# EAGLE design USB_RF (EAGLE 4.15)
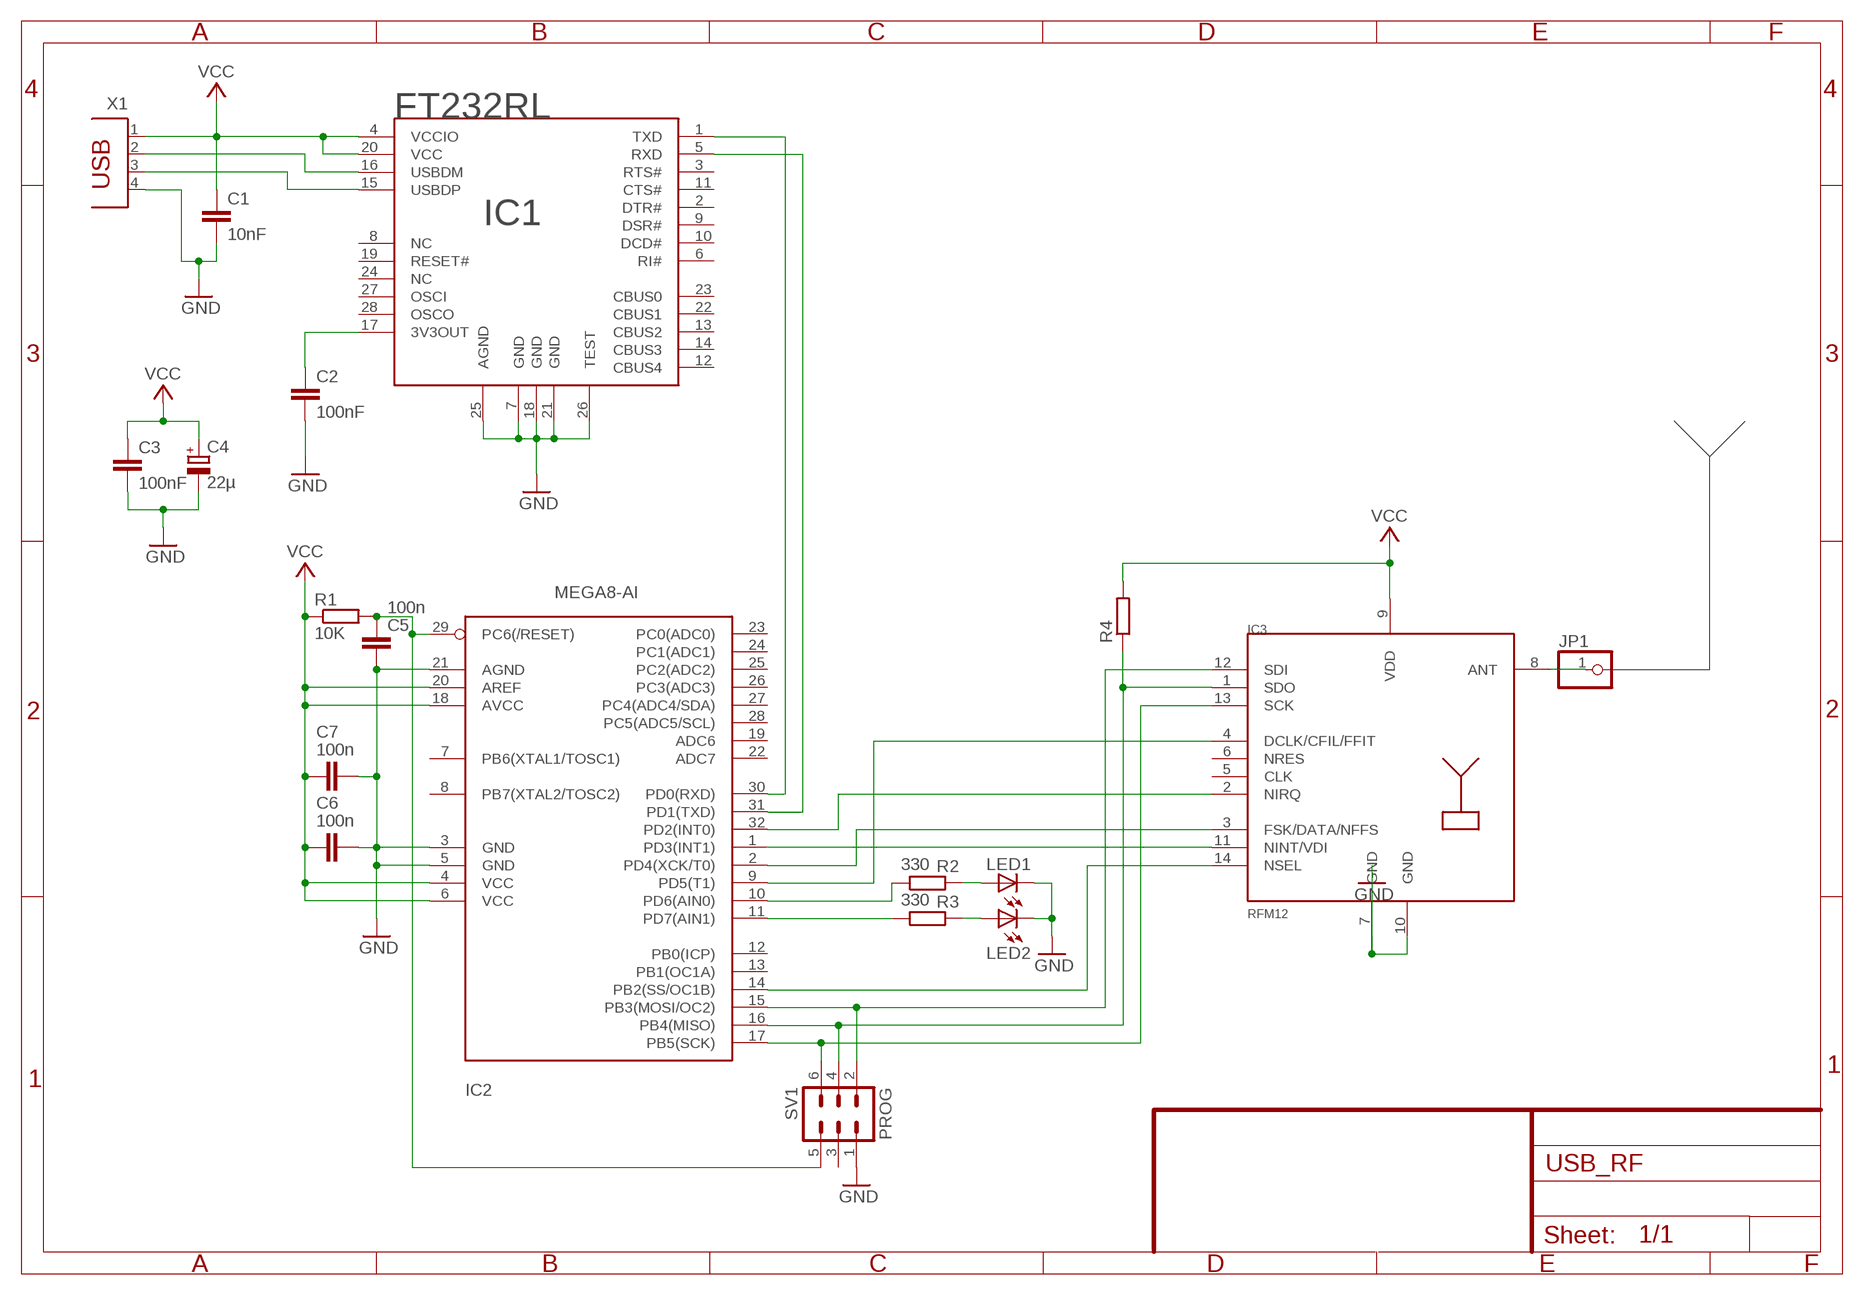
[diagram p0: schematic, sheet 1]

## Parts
C1  10nF  C-EUC0805  [C0805]
C2  100nF  C-EUC0805  [C0805]
C3  100nF  C-EUC0805  [C0805]
C4  22µ  CPOL-EU085CS-1AR  [085CS_1AR]
C5  100n  C-EUC0805  [C0805]
C6  100n  C-EUC0805  [C0805]
C7  100n  C-EUC0805  [C0805]
IC1  FT232RL  [SSOP28]
IC2  MEGA8-AI  [TQFP32-08]
IC3  RFM12  [RFM]
JP1  PINHD-1X1  [1X01]
LED1  LED3MM  [LED3MM]
LED2  LED3MM  [LED3MM]
R1  10K  R-EU_M0805  [M0805]
R2  330  R-EU_M0805  [M0805]
R3  330  R-EU_M0805  [M0805]
R4  R-EU_M0805  [M0805]
SV1  PROG  MA03-2  [MA03-2]
X1  PN61729  [PN61729]

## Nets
GND: C1.2 C2.2 C3.2 C4.- C5.2 C6.2 C7.2 IC1.7(GND) IC1.18(GND) IC1.21(GND) IC1.25(AGND) IC1.26(TEST) IC2.3(GND) IC2.5(GND) IC2.21(AGND) IC3.7(GND) IC3.10(GND) LED1.K(C) LED2.K(C) SV1.1 X1.4
N$1: IC1.16(USBDM) X1.2
N$2: IC1.15(USBDP) X1.3
N$4: IC1.1(TXD) IC2.30(PD0(RXD))
N$5: C2.1 IC1.17(3V3OUT)
N$6: IC1.5(RXD) IC2.31(PD1(TXD))
N$7: C5.1 IC2.29(PC6(/RESET)) R1.2 SV1.5
N$8: LED1.A R2.2
N$9: LED2.A R3.2
N$10: IC2.17(PB5(SCK)) IC3.13(SCK) SV1.6
N$11: IC2.16(PB4(MISO)) IC3.1(SDO) R4.1 SV1.4
N$12: IC2.15(PB3(MOSI/OC2)) IC3.12(SDI) SV1.2
N$13: IC2.10(PD6(AIN0)) R2.1
N$14: IC2.11(PD7(AIN1)) R3.1
N$15: IC2.9(PD5(T1)) IC3.4(DCLK/CFIL/FFIT)
N$17: IC2.32(PD2(INT0)) IC3.2(NIRQ)
N$18: IC2.2(PD4(XCK/T0)) IC3.3(FSK/DATA/NFFS)
N$19: IC2.1(PD3(INT1)) IC3.11(NINT/VDI)
N$20: IC3.8(ANT) JP1.1
N$21: IC2.14(PB2(SS/OC1B)) IC3.14(NSEL)
VCC: C1.1 C3.1 C4.+ C6.1 C7.1 IC1.4(VCCIO) IC1.20(VCC) IC2.4(VCC) IC2.6(VCC) IC2.18(AVCC) IC2.20(AREF) IC3.9(VDD) R1.1 R4.2 X1.1
Unconnected: IC1.2(DTR#) IC1.3(RTS#) IC1.6(RI#) IC1.8(NC) IC1.9(DSR#) IC1.10(DCD#) IC1.11(CTS#) IC1.12(CBUS4) IC1.13(CBUS2) IC1.14(CBUS3) IC1.19(RESET#) IC1.22(CBUS1) IC1.23(CBUS0) IC1.24(NC) IC1.27(OSCI) IC1.28(OSCO) IC2.7(PB6(XTAL1/TOSC1)) IC2.8(PB7(XTAL2/TOSC2)) IC2.12(PB0(ICP)) IC2.13(PB1(OC1A)) IC2.19(ADC6) IC2.22(ADC7) IC2.23(PC0(ADC0)) IC2.24(PC1(ADC1)) IC2.25(PC2(ADC2)) IC2.26(PC3(ADC3)) IC2.27(PC4(ADC4/SDA)) IC2.28(PC5(ADC5/SCL)) IC3.5(CLK) IC3.6(NRES) SV1.3

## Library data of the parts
C1-C3 C5-C7 = rcl:C-EU: CAPACITOR, European symbol
C4 = rcl:CPOL-EU: POLARIZED CAPACITOR, European symbol
IC1 = FTDI:FT232RL
IC2 = atmel:MEGA8: MICROCONTROLLER 8 Kbytes FLASH 1 kbytes SRAM 512 bytes EEPROM USART 6-channel 10 bit ADC 2-channel 8 bit ADC
IC3 = Pollin_RFMxx:RFM12
JP1 = pinhead:PINHD-1X1: PIN HEADER
LED1 LED2 = led:LED: LED
R1-R4 = rcl:R-EU_: RESISTOR, European symbol
SV1 = con-lstb:MA03-2: PIN HEADER
X1 = con-berg:PN61729: BERG USB connector

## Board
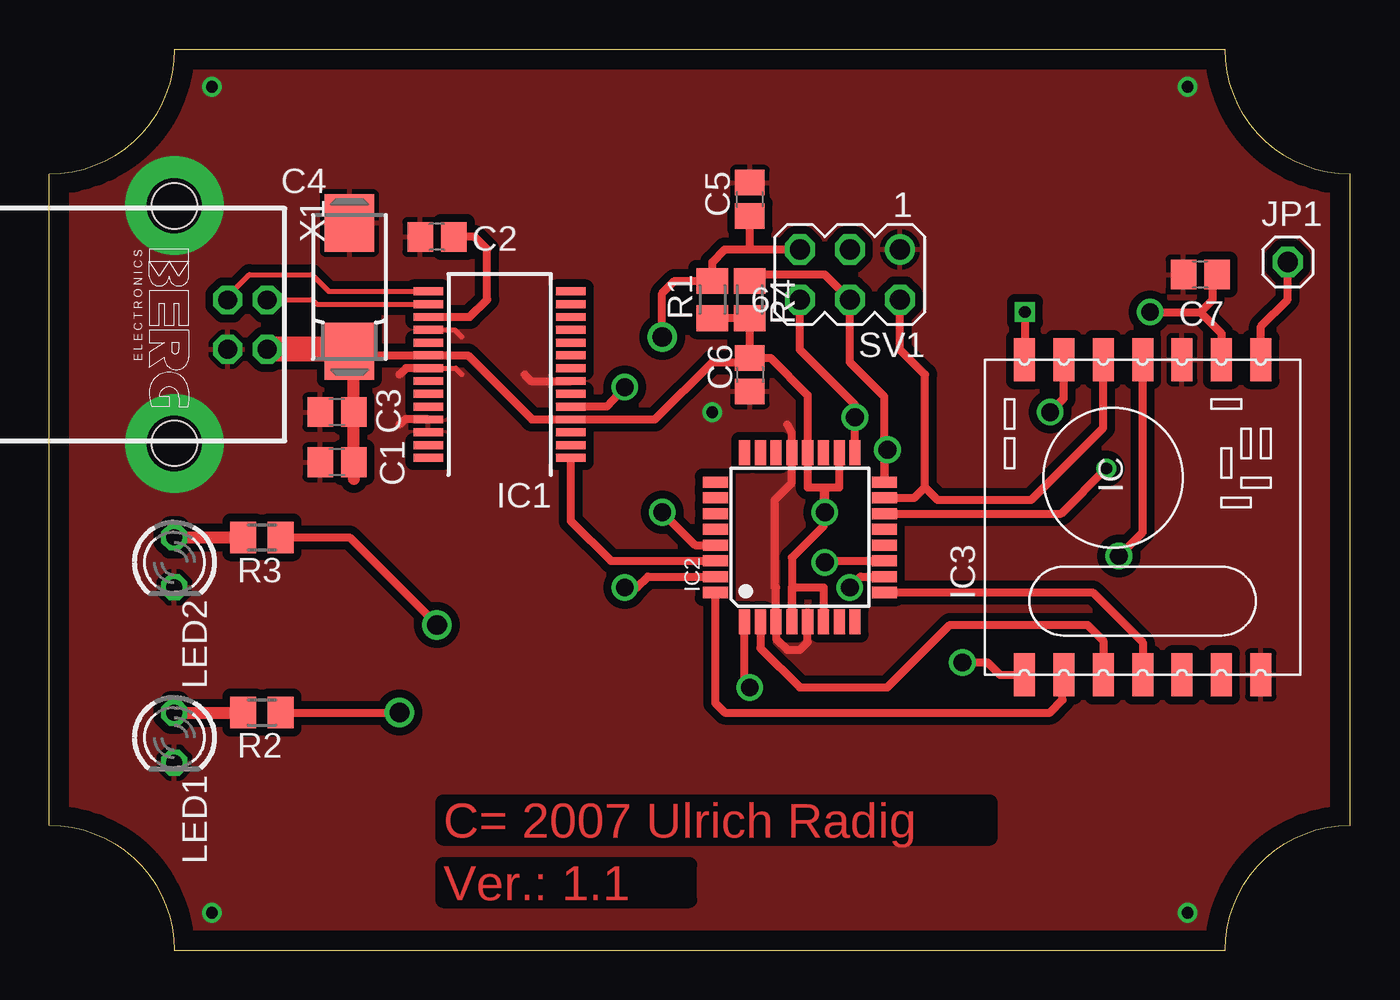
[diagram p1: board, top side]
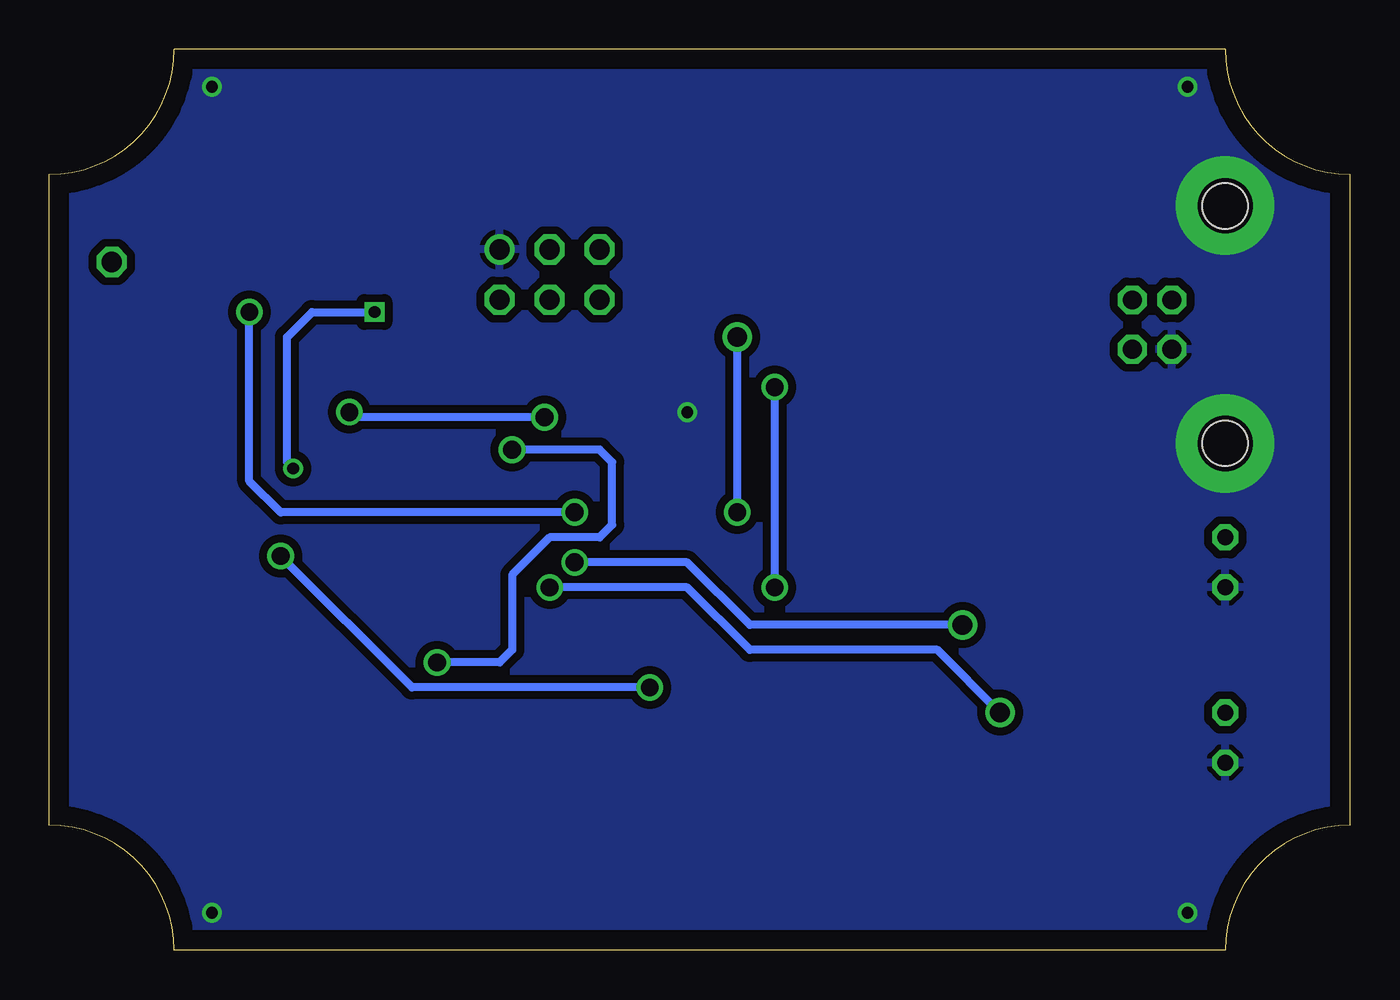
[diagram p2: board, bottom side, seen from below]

Size 66.04 x 45.72 mm. Coordinates in mm from the lower left corner, seen from the top.
Outline: 59.69,0 arc-90 66.04,6.35 66.04,39.37 arc-90 59.69,45.72 6.35,45.72 arc-90 0,39.37 0,6.35 arc-90 6.35,0 59.69,0
Copper layers (1*16): Top 0.035mm / dielectric 1.5mm / Bottom 0.035mm
Design rules "default": minimum track width 10mil, minimum drill 24mil, track to track 8mil, track to pad 8mil, pad to pad 8mil, via to via 8mil, smd to smd 8mil, copper to edge 40mil, drill to drill 8mil, minimum pad ring 10mil, minimum via ring 8mil, stop-mask expansion 4mil, vias tented up to drill 0mil, thermal gap 10mil

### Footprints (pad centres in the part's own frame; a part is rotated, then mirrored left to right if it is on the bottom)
C0805 = smd 1.3 x 1.5: 1 -0.85,0; 2 0.85,0
085CS_1AR = smd 2.9 x 2.5: + 3.25,0; - -3.25,0
SSOP28 = smd 0.4 x 1.5: 1 -4.225,-3.625; 2 -3.575,-3.625; 3 -2.925,-3.625; 4 -2.275,-3.625; 5 -1.625,-3.625; 6 -0.975,-3.625; 7 -0.325,-3.625; 8 0.325,-3.625; 9 0.975,-3.625; 10 1.625,-3.625; 11 2.275,-3.625; 12 2.925,-3.625; 13 3.575,-3.625; 14 4.225,-3.625; 15 4.225,3.625; 16 3.575,3.625; 17 2.925,3.625; 18 2.275,3.625; 19 1.625,3.625; 20 0.975,3.625; 21 0.325,3.625; 22 -0.325,3.625; 23 -0.975,3.625; 24 -1.625,3.625; 25 -2.275,3.625; 26 -2.925,3.625; 27 -3.575,3.625; 28 -4.225,3.625
TQFP32-08 = smd 1.27 x 0.559: 1 -4.293,2.8; 2 -4.293,2; 3 -4.293,1.2; 4 -4.293,0.4; 5 -4.293,-0.4; 6 -4.293,-1.2; 7 -4.293,-2; 8 -4.293,-2.8; 17 4.293,-2.8; 18 4.293,-2; 19 4.293,-1.2; 20 4.293,-0.4; 21 4.293,0.4; 22 4.293,1.2; 23 4.293,2; 24 4.293,2.8 | smd 0.559 x 1.27: 9 -2.8,-4.293; 10 -2,-4.293; 11 -1.2,-4.293; 12 -0.4,-4.293; 13 0.4,-4.293; 14 1.2,-4.293; 15 2,-4.293; 16 2.8,-4.293; 25 2.8,4.293; 26 2,4.293; 27 1.2,4.293; 28 0.4,4.293; 29 -0.4,4.293; 30 -1.2,4.293; 31 -2,4.293; 32 -2.8,4.293
RFM = smd 2.184 x 1.067: 1 0,14; 2 0,12; 3 0,10; 4 0,8; 5 0,6; 6 0,4; 7 0,2; 8 16,2; 9 16,4; 10 16,6; 11 16,8; 12 16,10; 13 16,12; 14 16,14
1X01 = drill 1.016 octagon: 1 0,0
LED3MM = drill 0.813 octagon: A -1.27,0; K 1.27,0
M0805 = smd 1.3 x 1.6: 1 -0.95,0; 2 0.95,0
MA03-2 = drill 1.016 round: 1 -2.54,-1.27 | drill 1.016 octagon: 2 -2.54,1.27; 3 0,-1.27; 4 0,1.27; 5 2.54,-1.27; 6 2.54,1.27
PN61729 = drill 0.95 octagon: 1 1.25,4.71; 2 -1.25,4.71; 3 -1.25,2.71; 4 1.25,2.71 | hole 2.3: -6.02,0; 6.02,0

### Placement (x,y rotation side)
C1  14.61,24.77 180 top
C2  19.68,36.2 180 top
C3  14.61,27.3 180 top
C4  15.24,33.66 270 top
C5  35.56,38.1 90 top
C6  35.56,29.21 270 top
C7  58.42,34.29 180 top
IC1  22.86,29.21 90 top
IC2  38.1,20.95 90 top
IC3  63.5,13.97 90 top
JP1  62.87,34.92 0 top
LED1  6.35,10.79 270 top
LED2  6.35,19.68 270 top
R1  33.66,33.02 90 top
R2  10.79,12.06 180 top
R3  10.79,20.95 180 top
R4  35.56,33.02 270 top
SV1  40.64,34.29 180 top
X1  6.35,31.75 270 top

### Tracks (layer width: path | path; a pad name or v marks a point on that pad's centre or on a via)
GND  (via drill 0.6, 2.8 pad 5)
  Top 0.254: IC1.21 20.63,29.54 20.95,29.21 | IC1.18 20.59,31.48 20.95,31.11
  Top 0.406: IC1.21 18.11,29.54 17.78,29.21 | IC1.25 18.05,26.93 17.78,26.67 | 37.47,26.67 37.7,26.27 IC2.21 37.7,23.73 36.83,22.86 36.83,18.41 36.9,18.41 IC2.3 36.9,15.8 37.47,15.24 38.1,15.24 38.5,15.64 IC2.5 | IC1.7 24.45,28.89 24.13,29.21
  other vias: 33.66,27.3 8.26,43.81 8.26,1.91 57.78,1.91 57.78,43.81 6.35,37.78 6.35,25.72
  pour Top (isolate 0.406): 0,45.72 66.04,45.72 66.04,0.64 0,0.64
  pour Bottom (isolate 0.406): 0,0 0,45.72 66.04,45.72 66.04,0
N$1
  Top 0.254: X1.2 13.31,33 13.34,33.02 13.57,32.78 IC1.16
N$2
  Top 0.254: IC1.15 14.19,33.44 13.34,34.29 10.16,34.29 8.89,33.02 8.91,33 X1.3
N$4
  Top 0.406: IC2.30 28.5,19.75 26.48,21.77 IC1.1
N$5
  Top 0.406: IC1.17 21.34,32.13 22.23,33.02 22.23,35.56 21.59,36.2 C2.1 20.32,36.2
N$6  (via drill 0.9)
  Top 0.406: IC1.5 28.3,27.59 v29.21,28.57 | v29.21,18.41 29.84,18.41 30.39,18.95 IC2.31
  Bottom 0.406: v29.21,18.41 v29.21,28.57
N$7  (via drill 0.9, 1)
  Top 0.406: IC2.29 32.78,20.55 v31.11,22.23 | v31.11,31.11 31.11,33.34 31.75,33.97 R1.2 33.66,34.92 34.29,35.56 35.56,35.56 | 35.56,35.56 C5.1 | 35.56,35.56 SV1.5
  Bottom 0.406: v31.11,22.23 v31.11,31.11
N$8
  Top 0.61: LED1.A R2.2
N$9
  Top 0.61: LED2.A R3.2
N$10  (via drill 0.9)
  Top 0.406: IC2.17 v40.9,27.05 40.9,27.68 40.64,27.94 38.1,30.48 SV1.6 | IC3.13 51.5,28 v50.8,27.3
  Bottom 0.406: v40.9,27.05 50.54,27.05 v50.8,27.3
N$11  (via drill 0.9)
  Top 0.406: v42.55,25.4 42.39,25.25 IC2.16 42.39,28.09 40.64,29.84 SV1.4 39.37,34.29 35.88,34.29 R4.1 | v46.35,14.61 47.62,14.61 48.26,13.97 IC3.1
  Bottom 0.406: v46.35,14.61 43.18,14.61 42.55,15.24 42.55,19.05 40.64,20.95 38.1,20.95 37.47,21.59 37.47,24.77 38.1,25.4 v42.55,25.4
N$12  (via drill 0.6)
  Top 0.406: IC3.12 53.5,26.51 49.85,22.86 45.09,22.86 44.45,23.5 | IC2.15 43.91,22.95 44.45,23.5 | 44.45,23.5 44.45,29.21 43.18,30.48 SV1.2
  other vias: 43.18,33.02
N$13  (via drill 0.9, 1)
  Top 0.406: IC2.10 41.18,18.95 v40.64,18.41 | R2.1 v17.78,12.06
  Bottom 0.406: v40.64,18.41 33.66,18.41 30.48,15.24 20.95,15.24 v17.78,12.06
N$14  (via drill 0.9, 1)
  Top 0.406: R3.1 15.24,20.95 v19.68,16.51 | IC2.11 39.3,19.75 v39.37,19.68
  Bottom 0.406: v19.68,16.51 30.48,16.51 33.66,19.68 v39.37,19.68
N$15
  Top 0.406: IC2.9 52.97,18.16 55.5,15.62 IC3.4
N$17
  Top 0.406: IC2.32 33.81,12.55 34.29,12.06 50.8,12.06 51.44,12.7 51.44,13.97 IC3.2
N$18
  Top 0.406: IC3.3 53.5,15.71 52.7,16.51 45.72,16.51 42.55,13.34 38.1,13.34 36.1,15.34 IC2.2
N$19  (via drill 0.9)
  Top 0.406: IC2.1 35.3,13.6 v35.56,13.34 | IC3.11 55.5,21.21 v54.29,20
  Bottom 0.406: v35.56,13.34 47.62,13.34 v54.29,20
N$20
  Top 0.406: IC3.8 61.5,31.66 62.87,33.02 JP1.1
N$21  (via drill 0.6)
  Top 0.406: IC2.14 51.37,22.16 v53.66,24.45 | IC3.14 49.5,29.88 49.53,29.84 v49.53,32.38
  Bottom 0.406: v53.66,24.45 53.98,24.77 53.98,31.11 52.7,32.38 v49.53,32.38
VCC  (via drill 0.9)
  Top 0.254: C3.1 15.24,27.3 15.46,27.09 | 15.46,30.27 15.24,30.48 15.54,30.18
  Top 0.305: C4.+ 15.24,30.48 15.22,30.5
  Top 0.406: 15.54,30.18 IC1.20 21.25,30.18 24.5,26.93 IC1.4 30.75,26.93 33.66,29.84 35.56,29.84 C6.1 | v55.88,32.38 58.42,32.38 | 58.42,32.38 59.05,33.02 59.05,34.29 C7.1 | IC3.9 59.5,31.3 58.42,32.38 | IC2.18 40.1,23.5 39.37,23.5 | 39.3,23.5 38.5,23.5 IC2.20 38.5,28.18 36.62,30.06 C6.1 | 39.3,23.5 39.37,23.5 | 39.37,23.5 v39.37,22.23 | C6.1 R4.2 | R4.2 R1.1 34.29,32.07 R4.2 | 39.3,23.5 39.3,21.52 37.7,19.92 IC2.4 37.7,18.41 39.3,18.41 IC2.6 | R4.2
  Top 0.61: 15.46,27.09 C1.1 15.46,23.91 | C3.1 15.46,30.27
  Top 1.27: 15.22,30.5 X1.1
  Bottom 0.406: v55.88,32.38 55.88,23.81 54.29,22.23 v39.37,22.23

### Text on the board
Top: C= 2007 Ulrich Radig | Ver.: 1.1
tStop: C= 2007 Ulrich Radig | Ver.: 1.1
